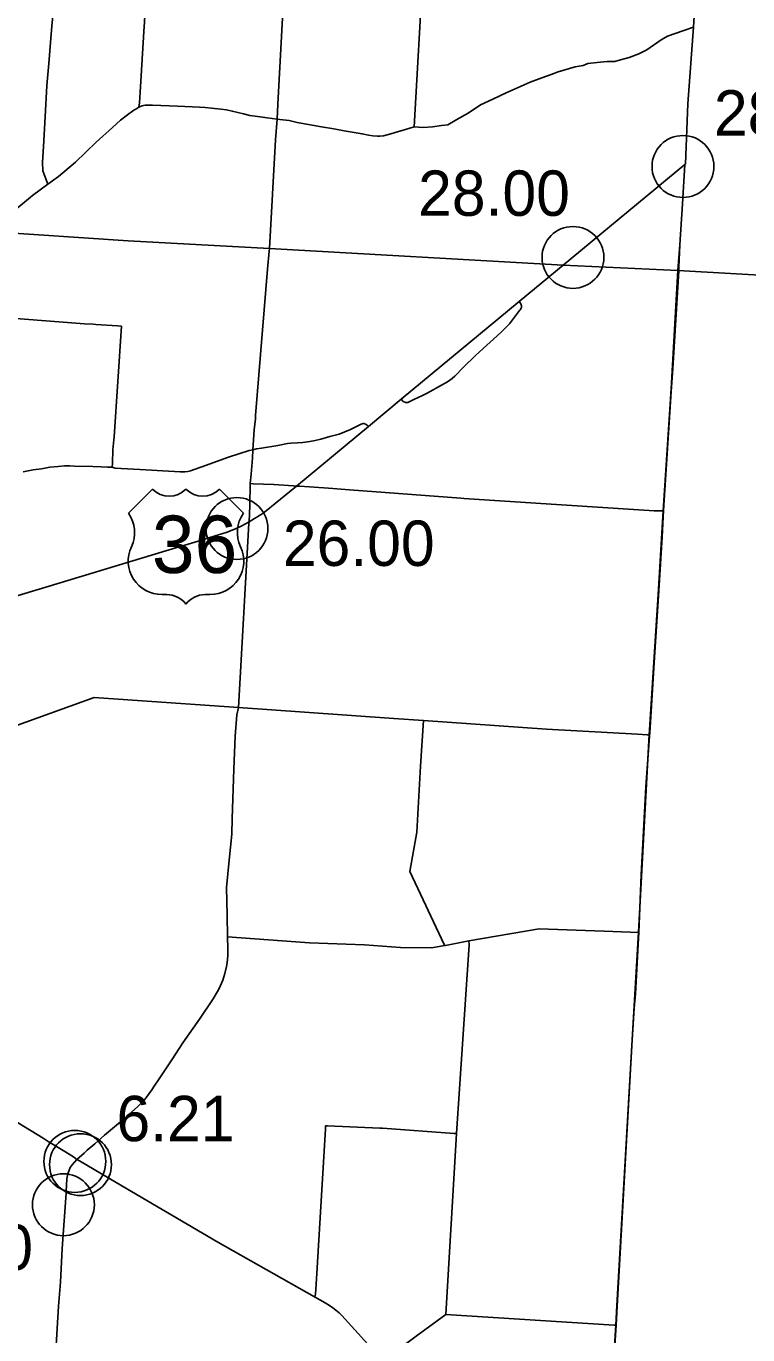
# Model space of a CAD drawing. Extents: x 1729596 to 1934326, y 644115 to 911751.
# Drawn here: x 1882714 to 1900207, y 803658 to 835395 of the extents above; entities that cross this region are included whole.
import ezdxf

# ---------------------------------------------------------------- set-up
doc = ezdxf.new("R2010")
doc.units = 0
for name, color, linetype in [('Default', 7, 'Continuous'), ('GM_X_Adjacent_County', 7, 'Continuous'), ('GM_X_County', 7, 'Continuous'), ('GM_X_County_Road', 7, 'Continuous'), ('GM_X_State_Route', 7, 'Continuous'), ('GM_X_Township', 7, 'Continuous'), ('GM_X_Township_Road', 7, 'Continuous'), ('GM_X_US_Route', 7, 'Continuous'), ('GM_X_US_Shield', 7, 'Continuous')]:
    doc.layers.add(name, color=color, linetype=linetype)

msp = doc.modelspace()

# ---------------------------------------------------------------- linework, layer by layer
at = {"layer": 'Default'}
for centre in [(1898635, 831992), (1895968, 829786), (1887823, 823212), (1883893, 807863), (1884030, 807785), (1883616, 806812)]:
    msp.add_circle(centre, 750, dxfattribs=at)
at = {"layer": 'GM_X_Adjacent_County'}
msp.add_line((1898513, 829466), (1915254, 828516), dxfattribs=at)
at = {"layer": 'GM_X_County'}
msp.add_lwpolyline([(1899202, 840435), (1898887, 835373), (1898754, 833509), (1898698, 832056), (1898677, 832037), (1898625, 831088), (1898557, 830092), (1898513, 829466), (1898352, 826597), (1898155, 823638), (1898045, 821739), (1897825, 818330), (1897815, 818218), (1897557, 813421), (1897406, 810815), (1897032, 804371), (1897004, 803896), (1896867, 801714)], dxfattribs=at)
at = {"layer": 'GM_X_County_Road'}
for points in [[(1888604, 829939), (1888609, 830001), (1888760, 832637), (1888800, 833137), (1888812, 833505), (1889049, 837835), (1889053, 837918), (1889133, 839176), (1889247, 841285), (1889264, 841582), (1889332, 842735), (1889339, 842955), (1889347, 843044), (1889371, 843177), (1889414, 843329), (1889428, 843400), (1889436, 843472), (1889534, 844778), (1889539, 844855)], [(1883240, 831567), (1883121, 831886), (1883110, 832097), (1883136, 832477), (1883174, 833194), (1883211, 833953), (1883259, 834488), (1883303, 835001), (1883338, 835393), (1883351, 835566), (1883352, 835653)], [(1883240, 831567), (1883496, 831745), (1883911, 832096), (1884413, 832583), (1884807, 832938), (1885003, 833112), (1885166, 833243), (1885326, 833358), (1885368, 833385), (1885446, 833427), (1885524, 833460), (1885556, 833468), (1885599, 833476), (1885624, 833478), (1885649, 833478), (1885778, 833475), (1886380, 833452), (1886918, 833430), (1887051, 833421), (1887207, 833409), (1887432, 833384), (1887568, 833364), (1887708, 833334), (1887981, 833265), (1888133, 833232), (1888203, 833219), (1888385, 833194), (1888553, 833173), (1888800, 833137), (1888866, 833133), (1889085, 833106), (1889281, 833061), (1889870, 832955), (1890175, 832901), (1890421, 832859), (1890857, 832781), (1891011, 832754), (1891116, 832738), (1891228, 832726), (1891289, 832726), (1891379, 832736), (1891557, 832782), (1891660, 832813), (1891907, 832887), (1892010, 832918), (1892122, 832957), (1892327, 832934), (1892566, 832957), (1892784, 832982), (1892937, 833003), (1893157, 833131), (1893427, 833287), (1893731, 833483), (1894025, 833628), (1894350, 833781), (1894712, 833939), (1894934, 834036), (1895214, 834140), (1895437, 834225), (1895608, 834291), (1896021, 834405), (1896215, 834443), (1896330, 834491), (1896557, 834514), (1896797, 834537), (1896986, 834540), (1897122, 834582), (1897333, 834631), (1897563, 834720), (1897761, 834818), (1898107, 835064), (1898263, 835149), (1898656, 835291), (1898887, 835373)], [(1898531, 829465), (1898535, 829554), (1898563, 830092), (1898625, 831088), (1898677, 832037)], [(1881648, 830290), (1881808, 830417), (1882869, 831288), (1883240, 831567)], [(1888211, 825123), (1888238, 825608), (1888269, 825875), (1888275, 825951), (1888566, 829499), (1888604, 829939)], [(1897822, 818179), (1897829, 818255), (1897948, 820090), (1898048, 821704), (1898128, 823007), (1898166, 823650), (1898353, 826531), (1898388, 827089), (1898531, 829465)], [(1891807, 826349), (1891855, 826296), (1891892, 826275), (1891910, 826271), (1891947, 826267), (1891967, 826270), (1892112, 826338), (1892322, 826440), (1892434, 826497), (1892779, 826687), (1892926, 826772), (1893037, 826849), (1893103, 826910), (1893327, 827129), (1893595, 827398), (1893703, 827499), (1893960, 827731), (1894216, 827965), (1894365, 828110), (1894427, 828179), (1894548, 828334), (1894670, 828497), (1894687, 828515), (1894710, 828555), (1894718, 828575), (1894723, 828595), (1894722, 828618), (1894713, 828640), (1894693, 828679), (1894662, 828715)], [(1882637, 824590), (1882881, 824632), (1883086, 824662), (1883290, 824696), (1883493, 824720), (1883640, 824734), (1883773, 824733), (1883887, 824727), (1884332, 824715), (1884531, 824707), (1884682, 824698), (1884802, 824698), (1884869, 824677), (1885617, 824633), (1886029, 824607), (1886447, 824588), (1886561, 824584), (1886629, 824591), (1886701, 824609), (1887064, 824744), (1887621, 824941), (1888121, 825102), (1888211, 825123), (1888301, 825141), (1888421, 825162), (1888813, 825227), (1889047, 825270), (1889140, 825279), (1889289, 825293), (1889417, 825300), (1889589, 825323), (1889719, 825344), (1889858, 825376), (1890073, 825441), (1890297, 825503), (1890440, 825558), (1890572, 825616), (1890734, 825693), (1890836, 825744), (1890880, 825758), (1890902, 825760), (1890937, 825746), (1890980, 825715), (1891009, 825686)], [(1888119, 823374), (1888136, 823770), (1888147, 824305), (1888170, 824530), (1888198, 824915), (1888211, 825123)], [(1888147, 824305), (1888213, 824298), (1888717, 824283), (1889192, 824249), (1889265, 824243)], [(1889265, 824243), (1889344, 824238), (1890044, 824187), (1890551, 824150), (1893249, 823947), (1893321, 823942), (1897937, 823643), (1898048, 823639), (1898076, 823638), (1898114, 823638), (1898140, 823641), (1898166, 823650)], [(1883945, 807913), (1884121, 808063), (1884192, 808137), (1884375, 808287), (1884615, 808499), (1884999, 808823), (1885413, 809183), (1885505, 809275), (1885580, 809356), (1885631, 809420), (1885760, 809600), (1885818, 809685), (1885938, 809865), (1886242, 810330), (1886511, 810739), (1886917, 811312), (1887249, 811810), (1887355, 811986), (1887375, 812027), (1887424, 812129), (1887477, 812258), (1887533, 812417), (1887573, 812593), (1887586, 812678), (1887600, 812854), (1887602, 813023), (1887597, 813309), (1887587, 813833), (1887573, 814503), (1887636, 815166), (1887701, 815803), (1887705, 816183), (1887748, 817374), (1887780, 818173), (1887818, 818696), (1887858, 818871), (1888113, 823336), (1888119, 823374)], [(1871277, 818480), (1872206, 818406), (1875525, 818156), (1880663, 817814), (1881619, 818131), (1884362, 819111), (1887858, 818871), (1889457, 818761), (1891623, 818604), (1892346, 818560), (1895326, 818344), (1897532, 818224), (1897769, 818211), (1897801, 818204), (1897822, 818179)], [(1897564, 813416), (1897624, 814812), (1897737, 816947), (1897822, 818179)], [(1896877, 801685), (1896878, 801713), (1896961, 803039), (1897015, 803890), (1897038, 804349), (1897401, 810812), (1897452, 811576), (1897482, 811930), (1897540, 812982), (1897564, 813416)]]:
    msp.add_lwpolyline(points, dxfattribs=at)
at = {"layer": 'GM_X_State_Route'}
for points in [[(1882507, 808811), (1883124, 808426), (1883245, 808350), (1883608, 808131), (1883859, 807974), (1883945, 807913)], [(1883681, 807137), (1883700, 807443), (1883727, 807565), (1883754, 807653), (1883783, 807713), (1883829, 807777), (1883885, 807848), (1883945, 807913)], [(1883945, 807913), (1884008, 807879), (1884894, 807348), (1887358, 805901), (1889702, 804583), (1889965, 804433), (1890068, 804367), (1890146, 804309), (1890221, 804252), (1890297, 804190), (1890369, 804123), (1890999, 803432), (1891373, 803023), (1891553, 802825), (1892288, 802025), (1892862, 801410), (1894115, 800116), (1894249, 799980), (1894338, 799884), (1894447, 799772), (1895444, 798735), (1896641, 797536)], [(1882720, 791504), (1882978, 795867), (1883003, 796429), (1883088, 797714), (1883392, 802588), (1883500, 804351), (1883543, 804938), (1883588, 805754), (1883679, 807097), (1883681, 807137)]]:
    msp.add_lwpolyline(points, dxfattribs=at)
at = {"layer": 'GM_X_Township'}
msp.add_lwpolyline([(1870008, 803514), (1870309, 808163), (1870779, 814239), (1870903, 816053), (1870933, 816495), (1870943, 816996), (1871003, 817857), (1871065, 818497), (1871124, 819057), (1871199, 820179), (1871965, 831096), (1873866, 830983), (1874715, 830911), (1874782, 830900), (1876113, 830808), (1881808, 830417), (1885186, 830186), (1888609, 830001), (1895732, 829600), (1898513, 829466)], dxfattribs=at)
at = {"layer": 'GM_X_Township_Road'}
for points in [[(1892122, 832957), (1892339, 836806), (1892341, 836860), (1892582, 840972), (1892585, 841036), (1892586, 841074), (1892651, 842825), (1892652, 842854), (1892658, 842912), (1892664, 842941), (1892680, 842997), (1892719, 843085), (1892728, 843106), (1892742, 843149), (1892749, 843194), (1892750, 843216), (1892770, 843468), (1892794, 843834), (1892869, 844984), (1892893, 845346)], [(1885446, 833427), (1885462, 833535), (1885473, 833796), (1885574, 835394), (1885580, 835487), (1885580, 835490), (1885581, 835505), (1885831, 839707), (1885835, 839776), (1885999, 842676), (1886002, 842745), (1886125, 844378), (1886129, 844439)], [(1880432, 828452), (1880452, 828445), (1880516, 828438), (1880549, 828431), (1880745, 828411), (1881545, 828362), (1882567, 828296), (1884124, 828178)], [(1884124, 828178), (1884130, 828177), (1884339, 828164), (1884399, 828160), (1884926, 828125), (1885023, 828118), (1884844, 825432), (1884839, 825362), (1884813, 825123), (1884810, 824800), (1884802, 824698)], [(1892877, 813100), (1892856, 813096), (1892847, 813127), (1892013, 814894), (1892187, 815844), (1892275, 817450), (1892346, 818560)], [(1893446, 813209), (1895152, 813500), (1896723, 813446), (1897564, 813416)], [(1887597, 813309), (1889585, 813162), (1890912, 813114), (1891786, 813054), (1892545, 813045), (1892856, 813096)], [(1891373, 803023), (1891387, 803039), (1891405, 803057), (1892171, 803626), (1892889, 804151), (1893142, 808538), (1893444, 812998), (1893450, 813114), (1893446, 813209)], [(1893446, 813209), (1892877, 813100)], [(1889702, 804583), (1889716, 804612), (1889727, 804647), (1889746, 804884), (1889770, 805286), (1889966, 808657), (1889971, 808727), (1890002, 808726), (1890019, 808725)], [(1890019, 808725), (1891290, 808671), (1891349, 808669), (1893087, 808542), (1893142, 808538)], [(1892889, 804151), (1896968, 803896), (1897015, 803890)]]:
    msp.add_lwpolyline(points, dxfattribs=at)
at = {"layer": 'GM_X_US_Route'}
msp.add_lwpolyline([(1880687, 821035), (1883192, 821790), (1886098, 822667), (1886884, 822903), (1887402, 823063), (1887564, 823117), (1887787, 823203), (1887941, 823279), (1888119, 823374), (1888248, 823452), (1888302, 823484), (1888354, 823517), (1888407, 823552), (1888458, 823588), (1888528, 823642), (1888751, 823815), (1889265, 824243), (1891009, 825686), (1891807, 826349), (1894662, 828715), (1895732, 829600), (1898677, 832037), (1898698, 832056)], dxfattribs=at)
at = {"layer": 'GM_X_US_Shield'}
for p, q in [((1885775, 824163), (1885195, 823583)), ((1885775, 824163), (1885195, 823583)), ((1887980, 823583), (1887400, 824163)), ((1887980, 823583), (1887400, 824163)), ((1886007, 821611), (1886123, 821611)), ((1886007, 821611), (1886123, 821611)), ((1887051, 821611), (1887167, 821611)), ((1887051, 821611), (1887167, 821611))]:
    msp.add_line(p, q, dxfattribs=at)
for centre, radius, start, end in [((1886181, 824577), 580, 225.573, 314.427), ((1886181, 824577), 580, 225.573, 314.427), ((1886993, 824577), 580, 225.573, 314.427), ((1886993, 824577), 580, 225.573, 314.427), ((1884530, 823117), 812, 334.5471, 35.0009), ((1884530, 823117), 812, 334.5471, 35.0009), ((1888645, 823117), 812, 144.9991, 205.4529), ((1888645, 823117), 812, 144.9991, 205.4529), ((1885998, 822423), 812, 154.8319, 270.6383), ((1885998, 822423), 812, 154.8319, 270.6383), ((1887177, 822423), 812, 269.3617, 25.1681), ((1887177, 822423), 812, 269.3617, 25.1681), ((1886123, 821030), 580, 36.8699, 90), ((1886123, 821030), 580, 36.8699, 90), ((1887051, 821030), 580, 90, 143.1301), ((1887051, 821030), 580, 90, 143.1301)]:
    msp.add_arc(centre, radius, start, end, dxfattribs=at)

# ---------------------------------------------------------------- texts
at = {"layer": 'Default'}
for s, p in [('28.66', (1899385, 832742)), ('28.00', (1892214, 830795)), ('26.00', (1888935, 822305)), ('6.21', (1884902, 808354)), ('6.00', (1880016, 805231))]:
    msp.add_text(s, height=1100, dxfattribs=at).set_placement(p)
at = {"layer": 'GM_X_US_Shield'}
msp.add_text('36', height=1392.2, dxfattribs=at).set_placement((1885760, 822133))
msp.add_text('36', height=1392.2, dxfattribs=at).set_placement((1885760, 822133))

doc.saveas('drawing.dxf')
